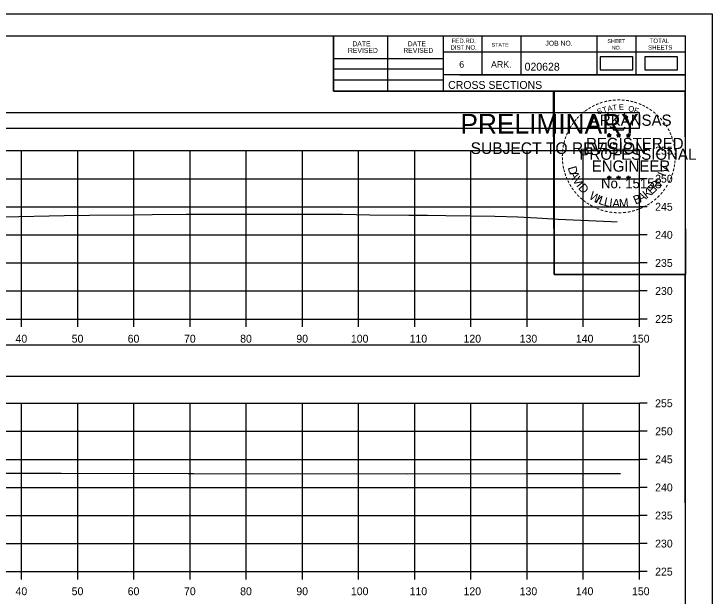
# Model space of a CAD drawing. Extents: x 1369627 to 1374022, y 380035 to 398173.
# Drawn here: x 1370217.9 to 1370342.2, y 381851.2 to 381954.9 of the extents above; entities that cross this region are included whole.
import ezdxf

# ---------------------------------------------------------------- set-up
doc = ezdxf.new("R2010")
doc.units = 0
for name, color, linetype in [('Default', 7, 'Continuous'), ('R_Axis', 7, 'Continuous'), ('R_Axis Annot', 7, 'Continuous'), ('R_Border', 7, 'Continuous'), ('R_Border PE', 7, 'Continuous'), ('R_Border Prem', 7, 'Continuous'), ('R_Exist Surface', 7, 'Continuous'), ('R_Grid', 7, 'Continuous'), ('R_No Plot', 7, 'Continuous')]:
    doc.layers.add(name, color=color, linetype=linetype)

msp = doc.modelspace()

# ---------------------------------------------------------------- linework, layer by layer
at = {"layer": 'Default'}
for points in [[(1370322.23, 381944.98), (1370328.06, 381944.98), (1370328.06, 381947.29), (1370322.23, 381947.29)], [(1370330.19, 381944.98), (1370336.03, 381944.98), (1370336.03, 381947.29), (1370330.19, 381947.29)], [(1370029.24, 381934.56), (1370329.24, 381934.56), (1370329.24, 381937.27), (1370029.24, 381937.27)], [(1370029.24, 381890.39), (1370329.24, 381890.39), (1370329.24, 381895.91), (1370029.24, 381895.91)]]:
    msp.add_lwpolyline(points, close=True, dxfattribs=at)
at = {"layer": 'R_Axis'}
for p, q in [((1370329.24, 381900.56), (1370329.24, 381930.56)), ((1370330.64, 381930.56), (1370329.24, 381930.56)), ((1370330.64, 381925.56), (1370329.24, 381925.56)), ((1370330.64, 381920.56), (1370329.24, 381920.56)), ((1370330.64, 381915.56), (1370329.24, 381915.56)), ((1370330.64, 381910.56), (1370329.24, 381910.56)), ((1370330.64, 381905.56), (1370329.24, 381905.56)), ((1370029.24, 381900.56), (1370329.24, 381900.56)), ((1370219.24, 381899.16), (1370219.24, 381900.56)), ((1370229.24, 381899.16), (1370229.24, 381900.56)), ((1370239.24, 381899.16), (1370239.24, 381900.56)), ((1370249.24, 381899.16), (1370249.24, 381900.56)), ((1370259.24, 381899.16), (1370259.24, 381900.56)), ((1370269.24, 381899.16), (1370269.24, 381900.56)), ((1370279.24, 381899.16), (1370279.24, 381900.56)), ((1370289.24, 381899.16), (1370289.24, 381900.56)), ((1370299.24, 381899.16), (1370299.24, 381900.56)), ((1370309.24, 381899.16), (1370309.24, 381900.56)), ((1370319.24, 381899.16), (1370319.24, 381900.56)), ((1370329.24, 381899.16), (1370329.24, 381900.56)), ((1370330.64, 381900.56), (1370329.24, 381900.56)), ((1370329.24, 381855.56), (1370329.24, 381885.56)), ((1370330.64, 381885.56), (1370329.24, 381885.56)), ((1370330.64, 381880.56), (1370329.24, 381880.56)), ((1370330.64, 381875.56), (1370329.24, 381875.56)), ((1370330.64, 381870.56), (1370329.24, 381870.56)), ((1370330.64, 381865.56), (1370329.24, 381865.56)), ((1370330.64, 381860.56), (1370329.24, 381860.56)), ((1370029.24, 381855.56), (1370329.24, 381855.56)), ((1370219.24, 381854.16), (1370219.24, 381855.56)), ((1370229.24, 381854.16), (1370229.24, 381855.56)), ((1370239.24, 381854.16), (1370239.24, 381855.56)), ((1370249.24, 381854.16), (1370249.24, 381855.56)), ((1370259.24, 381854.16), (1370259.24, 381855.56)), ((1370269.24, 381854.16), (1370269.24, 381855.56)), ((1370279.24, 381854.16), (1370279.24, 381855.56)), ((1370289.24, 381854.16), (1370289.24, 381855.56)), ((1370299.24, 381854.16), (1370299.24, 381855.56)), ((1370309.24, 381854.16), (1370309.24, 381855.56)), ((1370319.24, 381854.16), (1370319.24, 381855.56)), ((1370329.24, 381854.16), (1370329.24, 381855.56)), ((1370330.64, 381855.56), (1370329.24, 381855.56))]:
    msp.add_line(p, q, dxfattribs=at)
at = {"layer": 'R_Border'}
for p, q in [((1370021.24, 381951.02), (1370337.42, 381951.02)), ((1370274.78, 381941.14), (1370274.78, 381951.02)), ((1370284.46, 381941.14), (1370284.46, 381951.02)), ((1370294.32, 381951.02), (1370294.32, 381941.14)), ((1370301.16, 381951.02), (1370301.16, 381944.08)), ((1370308.1, 381951.02), (1370308.1, 381944.08)), ((1370321.68, 381951.02), (1370321.68, 381944.08)), ((1370328.62, 381951.02), (1370328.62, 381944.08)), ((1370337.42, 381745.56), (1370337.42, 381951.02)), ((1370337.42, 381948.08), (1370294.32, 381948.08)), ((1370337.42, 381948.1), (1370337.42, 381948.1)), ((1370274.78, 381947), (1370294.32, 381947)), ((1370274.78, 381945.14), (1370294.32, 381945.14)), ((1370274.78, 381943.2), (1370294.32, 381943.2)), ((1370337.42, 381944.08), (1370294.32, 381944.08)), ((1370297.28, 381944.08), (1370337.42, 381944.08)), ((1370337.42, 381941.14), (1370274.78, 381941.14))]:
    msp.add_line(p, q, dxfattribs=at)
at = {"layer": 'R_Border PE'}
for p, q in [((1370323.5, 381933.4), (1370323.85, 381933.28)), ((1370323.5, 381933.4), (1370323.76, 381933.35)), ((1370323.5, 381933.4), (1370323.74, 381933.27)), ((1370323.64, 381932.99), (1370323.85, 381933.28)), ((1370323.64, 381932.99), (1370323.76, 381933.23)), ((1370323.64, 381932.99), (1370323.85, 381933.2)), ((1370323.85, 381933.65), (1370323.81, 381933.4)), ((1370323.85, 381933.28), (1370323.85, 381933.65)), ((1370323.85, 381933.65), (1370323.9, 381933.4)), ((1370324.2, 381933.4), (1370323.85, 381933.28)), ((1370324.07, 381932.99), (1370323.85, 381933.28)), ((1370324.07, 381932.99), (1370323.85, 381933.2)), ((1370324.2, 381933.4), (1370323.91, 381933.35)), ((1370324.07, 381932.99), (1370323.93, 381933.28)), ((1370324.2, 381933.4), (1370324, 381933.29)), ((1370325.17, 381933.4), (1370325.52, 381933.28)), ((1370325.17, 381933.4), (1370325.43, 381933.35)), ((1370325.17, 381933.4), (1370325.41, 381933.27)), ((1370325.31, 381932.99), (1370325.52, 381933.28)), ((1370325.31, 381932.99), (1370325.43, 381933.23)), ((1370325.31, 381932.99), (1370325.52, 381933.2)), ((1370325.52, 381933.65), (1370325.48, 381933.4)), ((1370325.52, 381933.28), (1370325.52, 381933.65)), ((1370325.52, 381933.65), (1370325.57, 381933.4)), ((1370325.87, 381933.4), (1370325.52, 381933.28)), ((1370325.74, 381932.99), (1370325.52, 381933.28)), ((1370325.74, 381932.99), (1370325.52, 381933.2)), ((1370325.87, 381933.4), (1370325.58, 381933.35)), ((1370325.74, 381932.99), (1370325.6, 381933.28)), ((1370325.87, 381933.4), (1370325.67, 381933.29)), ((1370326.94, 381933.38), (1370327.29, 381933.27)), ((1370326.94, 381933.38), (1370327.19, 381933.34)), ((1370326.94, 381933.38), (1370327.18, 381933.26)), ((1370327.07, 381932.98), (1370327.29, 381933.27)), ((1370327.07, 381932.98), (1370327.2, 381933.22)), ((1370327.07, 381932.98), (1370327.29, 381933.19)), ((1370327.29, 381933.64), (1370327.25, 381933.39)), ((1370327.29, 381933.27), (1370327.29, 381933.64)), ((1370327.29, 381933.64), (1370327.34, 381933.39)), ((1370327.63, 381933.38), (1370327.29, 381933.27)), ((1370327.5, 381932.98), (1370327.29, 381933.27)), ((1370327.5, 381932.98), (1370327.29, 381933.19)), ((1370327.63, 381933.38), (1370327.35, 381933.33)), ((1370327.5, 381932.98), (1370327.36, 381933.27)), ((1370327.63, 381933.38), (1370327.43, 381933.28)), ((1370323.5, 381925.82), (1370323.85, 381925.71)), ((1370323.5, 381925.82), (1370323.75, 381925.78)), ((1370323.5, 381925.82), (1370323.74, 381925.7)), ((1370323.63, 381925.41), (1370323.85, 381925.71)), ((1370323.63, 381925.41), (1370323.76, 381925.66)), ((1370323.63, 381925.41), (1370323.85, 381925.63)), ((1370323.85, 381926.08), (1370323.81, 381925.82)), ((1370323.85, 381925.71), (1370323.85, 381926.08)), ((1370323.85, 381926.08), (1370323.9, 381925.83)), ((1370324.2, 381925.82), (1370323.85, 381925.71)), ((1370324.06, 381925.41), (1370323.85, 381925.71)), ((1370324.06, 381925.41), (1370323.85, 381925.63)), ((1370324.2, 381925.82), (1370323.91, 381925.77)), ((1370324.06, 381925.41), (1370323.93, 381925.71)), ((1370324.2, 381925.82), (1370323.99, 381925.72)), ((1370325.17, 381925.82), (1370325.52, 381925.71)), ((1370325.17, 381925.82), (1370325.42, 381925.78)), ((1370325.17, 381925.82), (1370325.41, 381925.7)), ((1370325.3, 381925.41), (1370325.52, 381925.71)), ((1370325.3, 381925.41), (1370325.43, 381925.66)), ((1370325.3, 381925.41), (1370325.52, 381925.63)), ((1370325.52, 381926.08), (1370325.48, 381925.82)), ((1370325.52, 381925.71), (1370325.52, 381926.08)), ((1370325.52, 381926.08), (1370325.57, 381925.83)), ((1370325.87, 381925.82), (1370325.52, 381925.71)), ((1370325.73, 381925.41), (1370325.52, 381925.71)), ((1370325.73, 381925.41), (1370325.52, 381925.63)), ((1370325.87, 381925.82), (1370325.58, 381925.77)), ((1370325.73, 381925.41), (1370325.59, 381925.71)), ((1370325.87, 381925.82), (1370325.66, 381925.72)), ((1370326.94, 381925.81), (1370327.29, 381925.7)), ((1370326.94, 381925.81), (1370327.19, 381925.77)), ((1370326.94, 381925.81), (1370327.17, 381925.69)), ((1370327.07, 381925.4), (1370327.29, 381925.7)), ((1370327.07, 381925.4), (1370327.2, 381925.65)), ((1370327.07, 381925.4), (1370327.28, 381925.62)), ((1370327.29, 381926.07), (1370327.24, 381925.81)), ((1370327.5, 381925.4), (1370327.28, 381925.62)), ((1370327.29, 381925.7), (1370327.29, 381926.07)), ((1370327.29, 381926.07), (1370327.33, 381925.82)), ((1370327.63, 381925.81), (1370327.29, 381925.7)), ((1370327.5, 381925.4), (1370327.29, 381925.7)), ((1370327.63, 381925.81), (1370327.35, 381925.76)), ((1370327.5, 381925.4), (1370327.36, 381925.7)), ((1370327.63, 381925.81), (1370327.43, 381925.71))]:
    msp.add_line(p, q, dxfattribs=at)
for points in [[(1370323.55, 381937.27), (1370323.81, 381936.45)], [(1370327.06, 381936.35), (1370327.2, 381936.64), (1370326.51, 381936.61), (1370326.66, 381937.27), (1370323.55, 381937.27)], [(1370324.04, 381934.85), (1370324.04, 381934.76), (1370324.6, 381934.74), (1370324.55, 381934.27), (1370326.42, 381934.27), (1370326.62, 381934.81)], [(1370323.85, 381933.65), (1370324.07, 381932.99), (1370323.5, 381933.4), (1370324.2, 381933.4), (1370323.64, 381932.99), (1370323.85, 381933.65)], [(1370325.52, 381933.65), (1370325.74, 381932.99), (1370325.17, 381933.4), (1370325.87, 381933.4), (1370325.31, 381932.99), (1370325.52, 381933.65)], [(1370327.29, 381933.64), (1370327.5, 381932.98), (1370326.94, 381933.38), (1370327.63, 381933.38), (1370327.07, 381932.98), (1370327.29, 381933.64)], [(1370323.85, 381926.08), (1370324.06, 381925.41), (1370323.5, 381925.82), (1370324.2, 381925.82), (1370323.63, 381925.41), (1370323.85, 381926.08)], [(1370325.52, 381926.08), (1370325.73, 381925.41), (1370325.17, 381925.82), (1370325.87, 381925.82), (1370325.3, 381925.41), (1370325.52, 381926.08)], [(1370327.29, 381926.07), (1370327.5, 381925.4), (1370326.94, 381925.81), (1370327.63, 381925.81), (1370327.07, 381925.4), (1370327.29, 381926.07)]]:
    msp.add_lwpolyline(points, dxfattribs=at)
for centre, radius in [((1370323.85, 381933.28), 0.172), ((1370323.85, 381933.28), 0.145), ((1370323.85, 381933.28), 0.116), ((1370323.85, 381933.28), 0.0991), ((1370323.85, 381933.28), 0.0747), ((1370323.85, 381933.28), 0.0495), ((1370323.85, 381933.28), 0.0296), ((1370325.52, 381933.28), 0.172), ((1370325.52, 381933.28), 0.145), ((1370325.52, 381933.28), 0.116), ((1370325.52, 381933.28), 0.0991), ((1370325.52, 381933.28), 0.0747), ((1370325.52, 381933.28), 0.0495), ((1370325.52, 381933.28), 0.0296), ((1370327.29, 381933.27), 0.172), ((1370327.29, 381933.27), 0.145), ((1370327.29, 381933.27), 0.116), ((1370327.29, 381933.27), 0.0991), ((1370327.29, 381933.27), 0.0747), ((1370327.29, 381933.27), 0.0495), ((1370327.29, 381933.27), 0.0296), ((1370323.85, 381925.71), 0.172), ((1370323.85, 381925.71), 0.145), ((1370323.85, 381925.71), 0.116), ((1370323.85, 381925.71), 0.0991), ((1370323.85, 381925.71), 0.0747), ((1370323.85, 381925.71), 0.0495), ((1370323.85, 381925.71), 0.0296), ((1370325.52, 381925.71), 0.172), ((1370325.52, 381925.71), 0.145), ((1370325.52, 381925.71), 0.116), ((1370325.52, 381925.71), 0.0991), ((1370325.52, 381925.71), 0.0747), ((1370325.52, 381925.71), 0.0495), ((1370325.52, 381925.71), 0.0296), ((1370327.28, 381925.7), 0.172), ((1370327.28, 381925.7), 0.145), ((1370327.28, 381925.7), 0.116), ((1370327.28, 381925.7), 0.0991), ((1370327.28, 381925.7), 0.0747), ((1370327.28, 381925.7), 0.0495), ((1370327.28, 381925.7), 0.0296)]:
    msp.add_circle(centre, radius, dxfattribs=at)
at = {"layer": 'R_Exist Surface'}
for points in [[(1370216.09, 381918.75), (1370226.79, 381919), (1370231.34, 381919.05), (1370239.11, 381919.13), (1370242.47, 381919.2), (1370248.56, 381919.24), (1370257.42, 381919.24), (1370260.72, 381919.25), (1370262.36, 381919.26), (1370264.18, 381919.25), (1370276.35, 381919.23), (1370281.25, 381919.15), (1370288.21, 381919.09), (1370291.5, 381919.04), (1370294.79, 381918.98), (1370303.48, 381918.86), (1370307.58, 381918.75), (1370310.97, 381918.61), (1370314.76, 381918.36), (1370324.21, 381917.91), (1370325.26, 381917.9)], [(1370203.8, 381873.13), (1370226.28, 381873.08), (1370248.92, 381873.02), (1370249.84, 381873.02), (1370287.9, 381872.96), (1370309.13, 381873.02), (1370325.85, 381873.07)]]:
    msp.add_lwpolyline(points, dxfattribs=at)
at = {"layer": 'R_Grid'}
for p, q in [((1370029.24, 381930.56), (1370329.24, 381930.56)), ((1370219.24, 381900.56), (1370219.24, 381930.56)), ((1370229.24, 381900.56), (1370229.24, 381930.56)), ((1370239.24, 381900.56), (1370239.24, 381930.56)), ((1370249.24, 381900.56), (1370249.24, 381930.56)), ((1370259.24, 381900.56), (1370259.24, 381930.56)), ((1370269.24, 381900.56), (1370269.24, 381930.56)), ((1370279.24, 381900.56), (1370279.24, 381930.56)), ((1370289.24, 381900.56), (1370289.24, 381930.56)), ((1370299.24, 381900.56), (1370299.24, 381930.56)), ((1370309.24, 381900.56), (1370309.24, 381930.56)), ((1370319.24, 381900.56), (1370319.24, 381930.56)), ((1370329.24, 381900.56), (1370329.24, 381930.56)), ((1370029.24, 381925.56), (1370329.24, 381925.56)), ((1370029.24, 381920.56), (1370329.24, 381920.56)), ((1370029.24, 381915.56), (1370329.24, 381915.56)), ((1370029.24, 381910.56), (1370329.24, 381910.56)), ((1370029.24, 381905.56), (1370329.24, 381905.56)), ((1370029.24, 381900.56), (1370329.24, 381900.56)), ((1370029.24, 381885.56), (1370329.24, 381885.56)), ((1370219.24, 381855.56), (1370219.24, 381885.56)), ((1370229.24, 381855.56), (1370229.24, 381885.56)), ((1370239.24, 381855.56), (1370239.24, 381885.56)), ((1370249.24, 381855.56), (1370249.24, 381885.56)), ((1370259.24, 381855.56), (1370259.24, 381885.56)), ((1370269.24, 381855.56), (1370269.24, 381885.56)), ((1370279.24, 381855.56), (1370279.24, 381885.56)), ((1370289.24, 381855.56), (1370289.24, 381885.56)), ((1370299.24, 381855.56), (1370299.24, 381885.56)), ((1370309.24, 381855.56), (1370309.24, 381885.56)), ((1370319.24, 381855.56), (1370319.24, 381885.56)), ((1370329.24, 381855.56), (1370329.24, 381885.56)), ((1370029.24, 381880.56), (1370329.24, 381880.56)), ((1370029.24, 381875.56), (1370329.24, 381875.56)), ((1370029.24, 381870.56), (1370329.24, 381870.56)), ((1370029.24, 381865.56), (1370329.24, 381865.56)), ((1370029.24, 381860.56), (1370329.24, 381860.56)), ((1370029.24, 381855.56), (1370329.24, 381855.56))]:
    msp.add_line(p, q, dxfattribs=at)
at = {"layer": 'R_No Plot'}
for p, q in [((1370008.84, 381954.92), (1370342.17, 381954.92)), ((1370313.45, 381918.69), (1370313.45, 381918.69))]:
    msp.add_line(p, q, dxfattribs=at)
for points in [[(1370008.83, 381954.92), (1370342.17, 381954.92), (1370342.17, 381741.58), (1370008.83, 381741.58)], [(1370255.16, 381951.02), (1370274.78, 381951.02), (1370274.78, 381941.14), (1370290.89, 381941.14), (1370314.09, 381941.14), (1370314.09, 381908.47), (1370337.3, 381908.47), (1370337.42, 381745.56), (1370021.24, 381745.56), (1370021.24, 381951.02)], [(1370313.95, 381941.14), (1370337.3, 381941.14), (1370337.44, 381908.47), (1370314.09, 381908.47)]]:
    msp.add_lwpolyline(points, close=True, dxfattribs=at)

# ---------------------------------------------------------------- texts
at = {"layer": 'R_Axis Annot'}
for s, p in [('255', (1370332.04, 381929.86)), ('250', (1370332.04, 381924.86)), ('245', (1370332.04, 381919.86)), ('240', (1370332.04, 381914.86)), ('235', (1370332.04, 381909.86)), ('230', (1370332.04, 381904.86)), ('225', (1370332.04, 381899.86)), ('40', (1370218.15, 381896.36)), ('50', (1370228.15, 381896.36)), ('60', (1370238.12, 381896.36)), ('70', (1370248.15, 381896.36)), ('80', (1370258.15, 381896.36)), ('90', (1370268.15, 381896.36)), ('100', (1370277.87, 381896.36)), ('110', (1370288.32, 381896.36)), ('120', (1370297.92, 381896.36)), ('130', (1370307.92, 381896.36)), ('140', (1370317.92, 381896.36)), ('150', (1370327.92, 381896.36)), ('255', (1370332.04, 381884.86)), ('250', (1370332.04, 381879.86)), ('245', (1370332.04, 381874.86)), ('240', (1370332.04, 381869.86)), ('235', (1370332.04, 381864.86)), ('230', (1370332.04, 381859.86)), ('225', (1370332.04, 381854.86)), ('40', (1370218.15, 381851.36)), ('50', (1370228.15, 381851.36)), ('60', (1370238.12, 381851.36)), ('70', (1370248.15, 381851.36)), ('80', (1370258.15, 381851.36)), ('90', (1370268.15, 381851.36)), ('100', (1370277.87, 381851.36)), ('110', (1370288.32, 381851.36)), ('120', (1370297.92, 381851.36)), ('130', (1370307.92, 381851.36)), ('140', (1370317.92, 381851.36)), ('150', (1370327.92, 381851.36))]:
    msp.add_text(s, height=1.4, dxfattribs=at).set_placement(p)
at = {"layer": 'R_Border'}
for s, height, p in [('FED.RD.', 0.782, (1370295.8, 381949.74)), ('TOTAL', 0.782, (1370331.06, 381949.74)), ('DATE', 0.879, (1370278.12, 381949.16)), ('DATE', 0.879, (1370287.98, 381949.16)), ('DIST.NO.', 0.782, (1370295.6, 381948.56)), ('STATE', 0.684, (1370302.92, 381949.06)), ('JOB NO.', 0.879, (1370312.5, 381949.26)), ('SHEET', 0.684, (1370323.54, 381949.74)), ('NO.', 0.684, (1370324.32, 381948.56)), ('SHEETS', 0.782, (1370330.78, 381948.56)), ('REVISED', 0.879, (1370277.34, 381947.98)), ('REVISED', 0.879, (1370287.2, 381947.98)), ('6', 1.17, (1370297.16, 381945.34)), ('ARK.', 1.172, (1370302.82, 381945.34)), ('020628', 1.4, (1370308.8, 381944.82)), ('CROSS SECTIONS', 1.4, (1370295.18, 381941.57))]:
    msp.add_text(s, height=height, rotation=360, dxfattribs=at).set_placement(p)
at = {"layer": 'R_Border PE'}
for s, height, rotation, p in [('-', 1.6, 13.6301, (1370323.04, 381938.64)), ('-', 1.6, 10.2193, (1370323.72, 381938.8)), ('-', 1.6, 5.8968, (1370324.45, 381938.91)), ('-', 1.6, 0.1862, (1370325.22, 381938.99)), ('-', 1.6, 357.743, (1370325.95, 381938.97)), ('-', 1.6, 352.1617, (1370326.69, 381938.92)), ('-', 1.6, 347.2049, (1370327.41, 381938.8)), ('-', 1.6, 342.3362, (1370328.04, 381938.65)), ('-', 1.6, 34.0636, (1370320.43, 381937.44)), ('-', 1.6, 28.7918, (1370321.03, 381937.81)), ('-', 1.6, 24.3072, (1370321.66, 381938.13)), ('S', 1, 21.594, (1370321.9, 381936.95)), ('-', 1.6, 19.1761, (1370322.29, 381938.4)), ('T', 1, 16.4036, (1370322.81, 381937.28)), ('A', 1, 11.2132, (1370323.64, 381937.53)), ('T', 1, 6.0228, (1370324.49, 381937.7)), ('E', 1, 0.8323, (1370325.59, 381937.81)), ('O', 1, 350.4515, (1370327.2, 381937.6)), ('F', 1, 340.0707, (1370328.15, 381937.37)), ('-', 1.6, 337.8551, (1370328.78, 381938.42)), ('-', 1.6, 334.1211, (1370329.41, 381938.15)), ('-', 1.6, 329.6409, (1370329.99, 381937.87)), ('-', 1.6, 325.8627, (1370330.63, 381937.51)), ('-', 1.6, 42.9622, (1370318.94, 381936.25)), ('-', 1.6, 38.9507, (1370319.38, 381936.67)), ('-', 1.6, 36.2317, (1370319.85, 381937.05)), ('ARKANSAS', 2, 360, (1370320.4, 381934.99)), ('-', 1.6, 320.5297, (1370331.24, 381937.08)), ('-', 1.6, 315.5786, (1370331.84, 381936.6)), ('-', 1.6, 54.2325, (1370317.68, 381934.72)), ('-', 1.6, 50.6142, (1370318.09, 381935.29)), ('-', 1.6, 48.423, (1370318.49, 381935.78)), ('-', 1.6, 309.8797, (1370332.41, 381936.05)), ('-', 1.6, 306.6522, (1370332.93, 381935.44)), ('-', 1.6, 62.8713, (1370317.04, 381933.58)), ('-', 1.6, 58.0706, (1370317.35, 381934.2)), ('-', 1.4, 303.6753, (1370333.42, 381934.88)), ('-', 1.6, 299.6684, (1370333.74, 381934.27)), ('-', 1.6, 72.3945, (1370316.56, 381932.34)), ('-', 1.6, 67.7743, (1370316.78, 381932.97)), ('-', 1.6, 294.6628, (1370334.06, 381933.66)), ('-', 1.6, 290.5728, (1370334.32, 381933.08)), ('-', 1.6, 75.461, (1370316.37, 381931.63)), ('REGISTERED', 2, 360, (1370319.72, 381930.84)), ('-', 1.6, 285.1233, (1370334.55, 381932.5)), ('-', 1.6, 85.1863, (1370316.16, 381930.22)), ('-', 1.6, 81.2013, (1370316.23, 381930.91)), ('PROFESSIONAL', 2, 360, (1370318.57, 381928.93)), ('-', 1.6, 280.5493, (1370334.75, 381931.76)), ('-', 1.6, 276.5962, (1370334.92, 381930.99)), ('-', 1.6, 94.1959, (1370316.17, 381928.8)), ('-', 1.6, 89.0622, (1370316.13, 381929.52)), ('-', 1.6, 274.3301, (1370334.98, 381930.27)), ('-', 1.6, 269.9407, (1370335.01, 381929.64)), ('-', 1.6, 98.9479, (1370316.24, 381928.13)), ('ENGINEER', 2, 360, (1370320.76, 381926.81)), ('V', 1.54, 72.6573, (1370334.06, 381926.38)), ('-', 1.6, 260.9953, (1370334.92, 381928.32)), ('-', 1.6, 263.5172, (1370334.99, 381928.97)), ('-', 1.6, 101.7149, (1370316.37, 381927.4)), ('-', 1.6, 105.4578, (1370316.54, 381926.8)), ('D', 1.54, 286.2848, (1370316.46, 381927.54)), ('-', 1.6, 255.7626, (1370334.81, 381927.64)), ('-', 1.6, 109.0874, (1370316.75, 381926.17)), ('-', 1.6, 114.0643, (1370317.01, 381925.58)), ('A', 1.54, 292.7835, (1370316.76, 381926.53)), ('V', 1.54, 300.7936, (1370317.27, 381925.35)), ('No. 15158', 1.757, 360, (1370322.4, 381923.86)), ('I', 1.54, 69.0301, (1370333.83, 381925.84)), ('-', 1.6, 247.8887, (1370334.41, 381926.24)), ('-', 1.6, 252.8681, (1370334.63, 381926.92)), ('-', 1.6, 115.7289, (1370317.31, 381924.96)), ('-', 1.6, 120.4471, (1370317.67, 381924.37)), ('I', 1.54, 308.3502, (1370317.9, 381924.32)), ('D', 1.54, 311.9774, (1370318.25, 381923.85)), ('E', 1.54, 44.0175, (1370331.45, 381922.64)), ('R', 1.54, 50.3651, (1370332.18, 381923.35)), (',', 1.54, 57.4684, (1370332.91, 381924.23)), ('-', 1.6, 239.0712, (1370333.75, 381924.86)), ('-', 1.6, 244.6197, (1370334.14, 381925.62)), ('-', 1.6, 125.8934, (1370318.07, 381923.81)), ('-', 1.6, 130.7181, (1370318.53, 381923.26)), ('W', 1.54, 328.0731, (1370320.13, 381922.09)), ('K', 1.54, 36.9143, (1370330.54, 381921.95)), ('-', 1.6, 231.2538, (1370332.92, 381923.64)), ('-', 1.6, 233.8452, (1370333.35, 381924.21)), ('-', 1.6, 134.2238, (1370319.05, 381922.71)), ('-', 1.6, 138.9338, (1370319.57, 381922.25)), ('I', 1.54, 336.6877, (1370321.32, 381921.38)), ('L', 1.54, 340.3149, (1370321.85, 381921.13)), ('L', 1.54, 346.6625, (1370322.81, 381920.79)), ('I', 1.54, 353.0101, (1370323.8, 381920.55)), ('A', 1.54, 356.6373, (1370324.37, 381920.47)), ('M', 1.54, 4.6473, (1370325.66, 381920.41)), ('B', 1.54, 22.8589, (1370328.53, 381920.94)), ('A', 1.54, 28.9042, (1370329.42, 381921.31)), ('-', 1.6, 221.0851, (1370331.92, 381922.57)), ('-', 1.6, 225.7653, (1370332.44, 381923.08)), ('-', 1.6, 144.6463, (1370320.13, 381921.84)), ('-', 1.6, 148.0898, (1370320.69, 381921.47)), ('-', 1.6, 151.5704, (1370321.27, 381921.15)), ('-', 1.6, 154.6002, (1370321.79, 381920.9)), ('-', 1.6, 207.3568, (1370330.28, 381921.37)), ('-', 1.6, 212.2491, (1370330.83, 381921.71)), ('-', 1.6, 215.7363, (1370331.37, 381922.1)), ('-', 1.6, 158.5612, (1370322.42, 381920.65)), ('-', 1.6, 162.7983, (1370323.1, 381920.43)), ('-', 1.6, 167.5555, (1370323.82, 381920.27)), ('-', 1.6, 173.1155, (1370324.59, 381920.16)), ('-', 1.6, 176.5183, (1370325.34, 381920.11)), ('AAMU', 0.00002, 360, (1370325.45, 381920.4)), ('-', 1.6, 181.5918, (1370326.08, 381920.13)), ('-', 1.6, 185.8167, (1370326.89, 381920.2)), ('-', 1.6, 191.2858, (1370327.63, 381920.33)), ('-', 1.6, 195.4743, (1370328.36, 381920.53)), ('-', 1.6, 199.4643, (1370329.02, 381920.77)), ('-', 1.6, 204.2516, (1370329.65, 381921.05))]:
    msp.add_text(s, height=height, rotation=rotation, dxfattribs=at).set_placement(p)
at = {"layer": 'R_Border Prem'}
for s, height, p in [('PRELIMINARY', 3.5, (1370297.37, 381933.6)), ('DWB', 0.01, (1370298.12, 381935.45)), ('SUBJECT TO REVISION', 2.0751, (1370299.18, 381929.97))]:
    msp.add_text(s, height=height, rotation=360, dxfattribs=at).set_placement(p)

doc.saveas('drawing.dxf')
